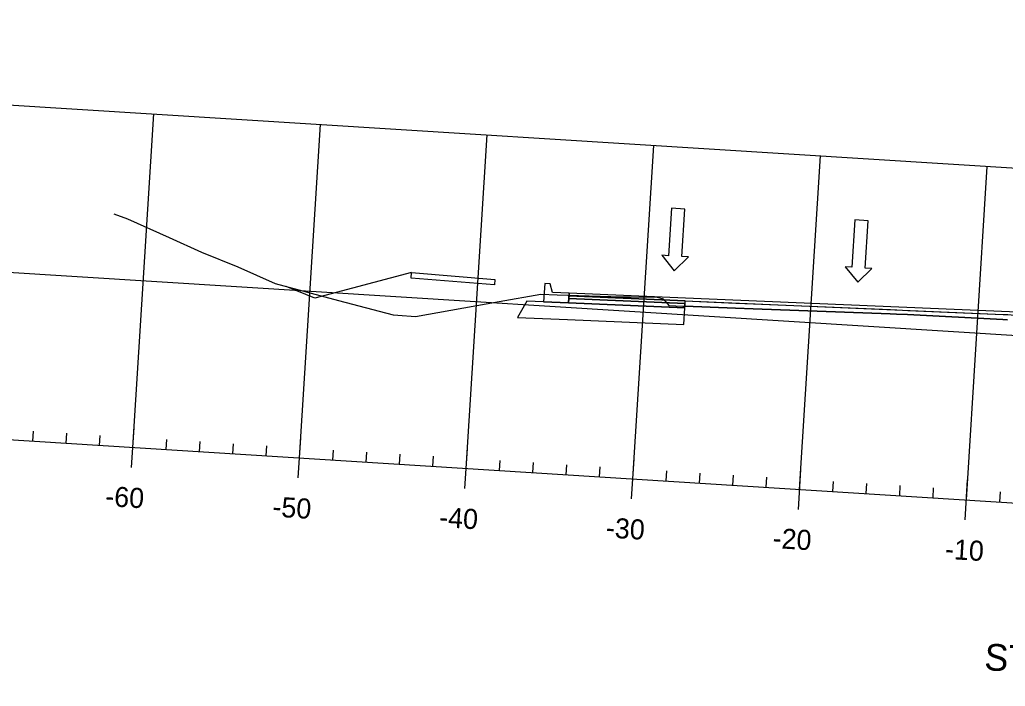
# Model space of a CAD drawing. Extents: x 658976 to 668721, y 639543 to 647196.
# Drawn here: x 660077.5 to 660372.5, y 642012 to 642211.4 of the extents above; entities that cross this region are included whole.
import ezdxf

# ---------------------------------------------------------------- set-up
doc = ezdxf.new("R2010")
doc.units = 0
for name, color, linetype in [('R_Axis', 7, 'Continuous'), ('R_Axis Annot', 7, 'Continuous'), ('R_Exist Surface', 7, 'Continuous'), ('R_Fin Surface', 7, 'Continuous'), ('R_Grid', 7, 'Continuous'), ('R_MOT', 7, 'Continuous'), ('R_Proposed Const Limits', 7, 'Continuous'), ('R_Proposed Road', 7, 'Continuous'), ('R_Sub Surface', 7, 'Continuous')]:
    doc.layers.add(name, color=color, linetype=linetype)

msp = doc.modelspace()

# ---------------------------------------------------------------- linework, layer by layer
msp.add_lwpolyline([(660241.98, 642129.64), (660236.99, 642129.85), (660236.31, 642132.4), (660234.65, 642132.5), (660234.31, 642127.05), (660241.8, 642126.73)], close=True)
at = {"layer": 'R_Axis'}
for p, q in [((659662.22, 642111.64), (661159.27, 642017.62)), ((660110.96, 642077.45), (660111.71, 642089.43)), ((660081.39, 642085.32), (660081.58, 642088.31)), ((660091.37, 642084.69), (660091.56, 642087.69)), ((660101.35, 642084.06), (660101.54, 642087.06)), ((660121.31, 642082.81), (660121.5, 642085.81)), ((660160.86, 642074.32), (660161.61, 642086.29)), ((660131.29, 642082.18), (660131.48, 642085.18)), ((660141.27, 642081.56), (660141.46, 642084.55)), ((660151.25, 642080.93), (660151.44, 642083.92)), ((660171.21, 642079.68), (660171.4, 642082.67)), ((660210.76, 642071.18), (660211.51, 642083.16)), ((660181.19, 642079.05), (660181.38, 642082.04)), ((660191.17, 642078.42), (660191.36, 642081.42)), ((660201.16, 642077.8), (660201.34, 642080.79)), ((660260.66, 642068.05), (660261.41, 642080.02)), ((660221.12, 642076.54), (660221.3, 642079.54)), ((660231.1, 642075.92), (660231.28, 642078.91)), ((660241.08, 642075.29), (660241.26, 642078.28)), ((660251.06, 642074.66), (660251.24, 642077.66)), ((660310.56, 642064.91), (660311.31, 642076.89)), ((660271.02, 642073.41), (660271.21, 642076.4)), ((660281, 642072.78), (660281.19, 642075.78)), ((660290.98, 642072.16), (660291.17, 642075.15)), ((660300.96, 642071.53), (660301.15, 642074.52)), ((660360.46, 642061.78), (660361.22, 642073.76)), ((660320.92, 642070.27), (660321.11, 642073.27)), ((660330.9, 642069.65), (660331.09, 642072.64)), ((660340.88, 642069.02), (660341.07, 642072.02)), ((660350.86, 642068.39), (660351.05, 642071.39)), ((660370.82, 642067.14), (660371.01, 642070.13))]:
    msp.add_line(p, q, dxfattribs=at)
at = {"layer": 'R_Exist Surface'}
msp.add_lwpolyline([(660105.68, 642153.33), (660109.73, 642151.81), (660122.23, 642146.29), (660131.92, 642141.85), (660142.75, 642137.51), (660153.93, 642132.51), (660172.96, 642127.41), (660189.27, 642123.17), (660190.71, 642123), (660195.97, 642122.63), (660221.02, 642127.13), (660233.52, 642129.36), (660238.39, 642129.15), (660257.63, 642128.5), (660260.36, 642128.5), (660268.25, 642128.43), (660269.06, 642128.2), (660270.12, 642127.91), (660270.85, 642127.04), (660271.8, 642125.9), (660276, 642125.74), (660276.6, 642125.73), (660291.7, 642125.1), (660297, 642124.89), (660338.01, 642123.44), (660339.98, 642123.36), (660343.27, 642123.2), (660371.72, 642121.74), (660373.17, 642121.68)], dxfattribs=at)
at = {"layer": 'R_Fin Surface'}
for points in [[(660276.64, 642126.49), (660241.88, 642127.98), (660241.8, 642126.73), (660276.56, 642125.24)], [(660276.7, 642127.32), (660241.93, 642128.81), (660241.88, 642127.98), (660276.64, 642126.49)]]:
    msp.add_lwpolyline(points, close=True, dxfattribs=at)
msp.add_lwpolyline([(660373.17, 642121.68), (660371.72, 642121.74), (660343.27, 642123.2), (660339.98, 642123.36), (660338.01, 642123.44), (660297, 642124.89), (660291.7, 642125.1), (660276.6, 642125.73), (660276.6, 642125.73), (660276.7, 642127.32), (660276.7, 642127.32), (660291.8, 642126.67), (660297.1, 642126.45), (660338.09, 642124.69), (660340.06, 642124.61), (660343.35, 642124.47), (660371.82, 642123.25), (660373.26, 642123.19)], dxfattribs=at)
at = {"layer": 'R_Grid'}
for p, q in [((659668.48, 642211.45), (661165.54, 642117.43)), ((660111.33, 642083.44), (660117.6, 642183.24)), ((660161.23, 642080.3), (660167.5, 642180.11)), ((660211.14, 642077.17), (660217.4, 642176.97)), ((660261.04, 642074.04), (660267.31, 642173.84)), ((660310.94, 642070.9), (660317.21, 642170.71)), ((660360.84, 642067.77), (660367.11, 642167.57)), ((659665.35, 642161.55), (661162.4, 642067.52)), ((659662.22, 642111.64), (661159.27, 642017.62))]:
    msp.add_line(p, q, dxfattribs=at)
at = {"layer": 'R_MOT'}
for p, q in [((660272.59, 642155.01), (660271.7, 642140.83)), ((660276.58, 642154.76), (660272.59, 642155.01)), ((660275.69, 642140.58), (660276.58, 642154.76)), ((660327.48, 642151.56), (660326.59, 642137.39)), ((660331.47, 642151.31), (660327.48, 642151.56)), ((660330.58, 642137.14), (660331.47, 642151.31)), ((660271.7, 642140.83), (660269.7, 642140.96)), ((660269.7, 642140.96), (660273.42, 642136.33)), ((660273.42, 642136.33), (660277.69, 642140.46)), ((660277.69, 642140.46), (660275.69, 642140.58)), ((660326.59, 642137.39), (660324.59, 642137.51)), ((660324.59, 642137.51), (660328.31, 642132.88)), ((660328.31, 642132.88), (660332.58, 642137.01)), ((660332.58, 642137.01), (660330.58, 642137.14))]:
    msp.add_line(p, q, dxfattribs=at)
at = {"layer": 'R_Proposed Const Limits'}
msp.add_lwpolyline([(660194.78, 642135.81), (660165.83, 642128.14), (660157.21, 642131.63)], dxfattribs=at)
msp.add_lwpolyline([(660241.98, 642129.64), (660241.93, 642128.81), (660276.7, 642127.32), (660406.82, 642121.76), (660406.87, 642122.59), (660276.75, 642128.15)], close=True, dxfattribs=at)
at = {"layer": 'R_Proposed Road'}
msp.add_lwpolyline([(660194.78, 642135.81), (660219.7, 642133.74), (660219.59, 642132.08), (660194.67, 642134.15)], close=True, dxfattribs=at)
at = {"layer": 'R_Sub Surface'}
msp.add_lwpolyline([(660276.56, 642125.24), (660241.8, 642126.73), (660234.31, 642127.05), (660229.31, 642127.26), (660226.47, 642122.38), (660241.49, 642121.74), (660276.25, 642120.25)], close=True, dxfattribs=at)

# ---------------------------------------------------------------- texts
at = {"layer": 'R_Axis Annot'}
for s, height, p in [('-60', 6, (660102.97, 642065.93)), ('-50', 6, (660153.01, 642062.78)), ('-40', 6, (660202.91, 642059.65)), ('-30', 6, (660252.82, 642056.52)), ('-20', 6, (660302.72, 642053.38)), ('-10', 6, (660354.31, 642050.14)), ('STA. 122+10.00', 8, (660366.06, 642016.84))]:
    msp.add_text(s, height=height, rotation=356.4063, dxfattribs=at).set_placement(p)

doc.saveas('drawing.dxf')
